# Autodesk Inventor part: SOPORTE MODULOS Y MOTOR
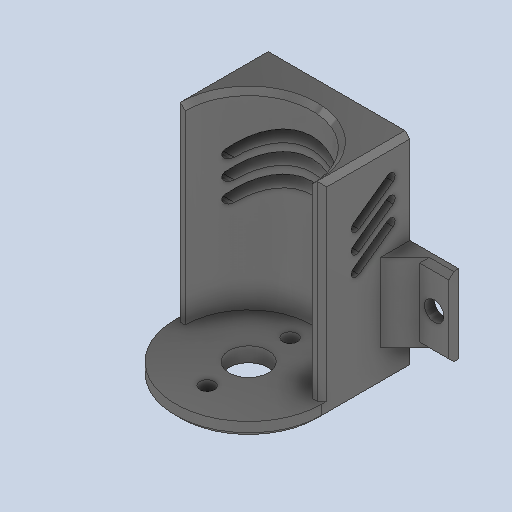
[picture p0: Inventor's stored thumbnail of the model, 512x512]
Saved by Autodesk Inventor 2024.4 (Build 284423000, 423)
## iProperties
Created: 2025-06
Part Number: SOPORTE MODULOS Y MOTOR
Material: Generic
Document SubType Name: Modeling
Designer: AdminForWorker
Density: 1 g/cm^3
Appearance: Default
Title: SOPORTE MODULOS Y MOTOR v14
Author: AdminForWorker
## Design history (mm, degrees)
feature "MOTOR"
body "Solid1"
